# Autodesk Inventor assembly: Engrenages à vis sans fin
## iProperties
Created: 2011-10
Part Number: Engrenages à vis sans fin
Document SubType Name: Assembly
Designer: Laur
ClientObjectVersion: 1
Author: Laur
